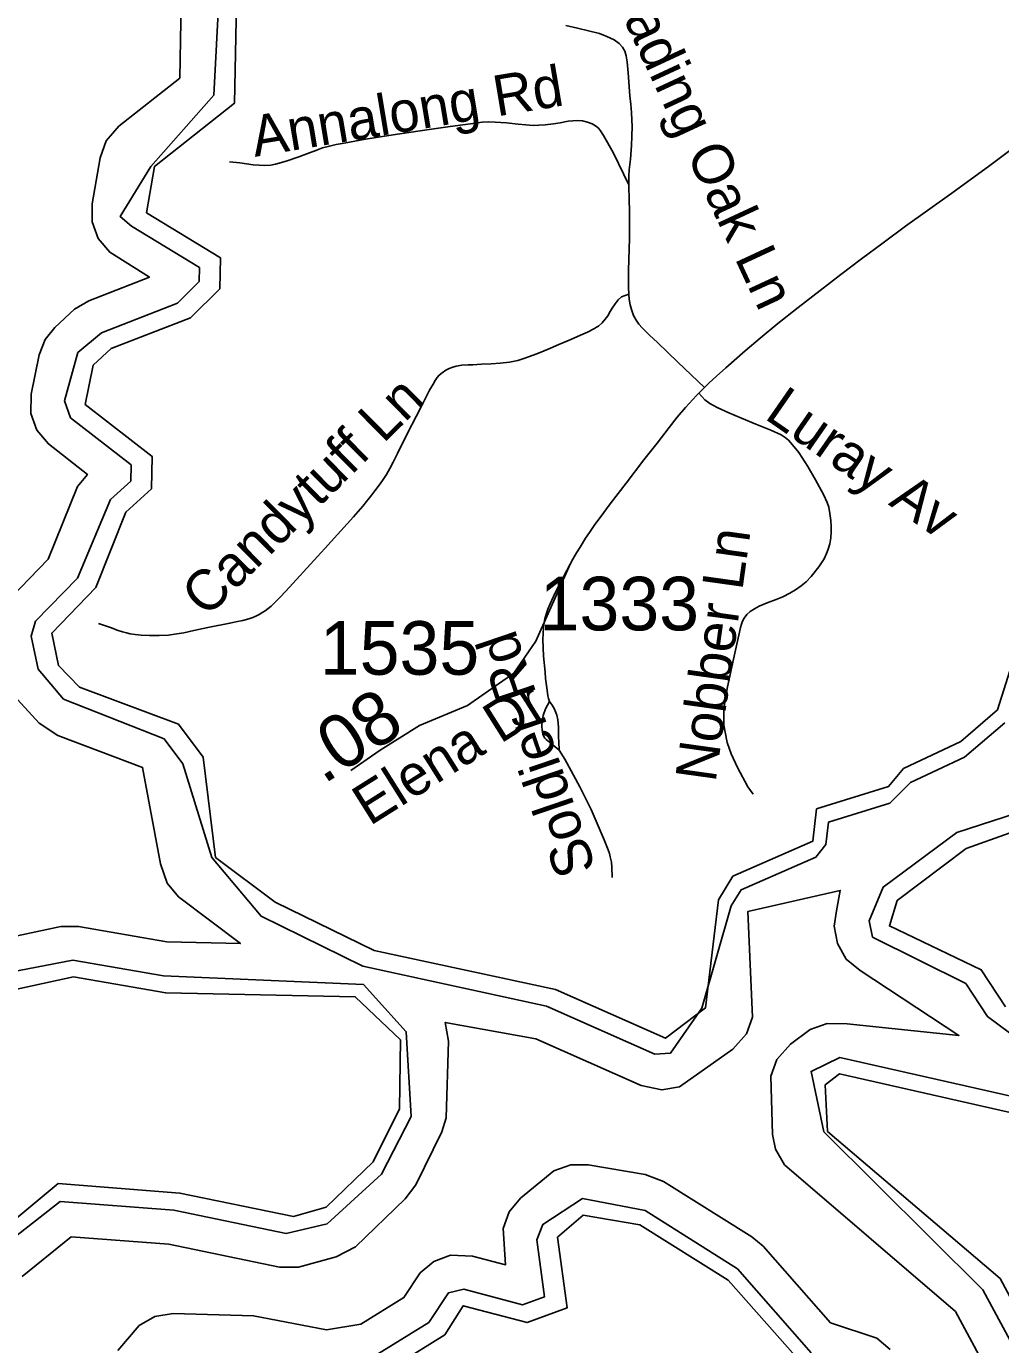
# Model space of a CAD drawing. Extents: x 1383679 to 1536984, y 460658 to 651027.
# Drawn here: x 1393235 to 1395507, y 499394 to 502468 of the extents above; entities that cross this region are included whole.
import ezdxf

# ---------------------------------------------------------------- set-up
doc = ezdxf.new("R2010")
doc.units = 0
for name, color, linetype in [('Exist Hydrographic Bay Label', 7, 'Continuous'), ('Exist Hydrographic Buffer Line', 7, 'Continuous'), ('Exist Hydrographic Island Shore', 7, 'Continuous'), ('Exist Road Non-System Type 51', 7, 'Continuous'), ('Exist Road Non-System Type 51 Label', 7, 'Continuous'), ('Exist Road Secondary Mileage Hundredths English Label', 7, 'Continuous'), ('Exist Road Secondary Type 51 Attributed', 7, 'Continuous'), ('Exist Road Secondary Type 51 Label', 7, 'Continuous'), ('Exist Road Secondary Type 51 Number Label', 7, 'Continuous')]:
    doc.layers.add(name, color=color, linetype=linetype)

msp = doc.modelspace()

# ---------------------------------------------------------------- linework, layer by layer
at = {"layer": 'Exist Hydrographic Bay Label'}
for points in [[(1395563, 501073.2), (1395500, 500874.2), (1395415, 500800.4), (1395281, 500737.4), (1395246, 500695.4), (1395078.1, 500643), (1395069.1, 500567.7), (1394883.1, 500486.1), (1394849.1, 500431), (1394819, 500178.8), (1394726, 500108.5), (1394469.1, 500222), (1394046.1, 500312.5), (1393815.1, 500425.5), (1393676.1, 500530), (1393647.1, 500763.7), (1393590.2, 500840.3), (1393359.2, 500927), (1393310.2, 500977.2), (1393294.2, 501053), (1393397.1, 501159.3), (1393467.2, 501335.1), (1393527.1, 501389.7), (1393528.2, 501465.2), (1393372.1, 501586.5), (1393391.2, 501678), (1393433.1, 501716.5), (1393618.2, 501788.3), (1393686.2, 501855.9), (1393688.1, 501928.1), (1393515.1, 502033.3), (1393534.1, 502141.2), (1393720.2, 502288.5), (1393725.1, 502521.4)], [(1395519.1, 500181.2), (1395462.1, 500267.7), (1395248.1, 500370.4), (1395266, 500429.2), (1395427, 500550.7), (1395628, 500622.1)], [(1395098.1, 499999.3), (1395132, 500024.9), (1395547, 499931.2)], [(1395610, 499355.4), (1395506, 499547.9), (1395104, 499890.9), (1395098.1, 499999.3)], [(1394067.1, 499327.4), (1394211.1, 499416.4), (1394254.1, 499484.5), (1394403.1, 499445.3), (1394496.1, 499479.6), (1394474, 499644.1), (1394534.1, 499695.5), (1394666.1, 499673.1), (1394872, 499544.3), (1395052.1, 499340.4)]]:
    msp.add_lwpolyline(points, dxfattribs=at)
at = {"layer": 'Exist Hydrographic Buffer Line'}
for points in [[(1393684.8, 502545.4), (1393672, 502307.8), (1393525.4, 502140.9), (1393454.2, 502024.5), (1393480.7, 502002.3), (1393638.8, 501905.6), (1393637.9, 501872.6), (1393587.3, 501822.2), (1393410, 501753.4), (1393355.5, 501707.1), (1393324.3, 501594.3), (1393337.7, 501555.4), (1393479.2, 501445.4), (1393478.7, 501407.2), (1393431.5, 501364.3), (1393354.2, 501181.1), (1393256.8, 501080.5), (1393246.2, 501045.7), (1393262.4, 500968.6), (1393321.9, 500898.7), (1393556.4, 500806.6), (1393600, 500747.9), (1393667.4, 500529.7), (1393782.4, 500393.1), (1394019.9, 500276.2), (1394448.1, 500183.3), (1394701.2, 500071.5), (1394737.4, 500073.4), (1394810.4, 500178.4), (1394879.1, 500417.1), (1394902, 500454), (1395076.6, 500530.7), (1395099.8, 500560.4), (1395106.1, 500612.2), (1395249.3, 500656.8), (1395297.4, 500704.5), (1395423.4, 500763.7), (1395517.6, 500843.6)], [(1393596.5, 502523.6), (1393592.7, 502347.2), (1393451, 502235), (1393421.5, 502200.8), (1393407.2, 502161.7), (1393388.3, 502053.7), (1393388.3, 502012.1), (1393402.5, 501972.9), (1393429.4, 501941), (1393522.3, 501882.9), (1393381.1, 501828), (1393347.4, 501808.1), (1393301.3, 501766), (1393278.6, 501737.6), (1393265, 501702.1), (1393246, 501610.6), (1393245.2, 501565.3), (1393259.5, 501526.1), (1393286.4, 501494.2), (1393377.5, 501423.2), (1393354.5, 501394.7), (1393285.7, 501225.4), (1393199.3, 501136.2)], [(1393197.6, 500916.9), (1393264.7, 500842.8), (1393308.4, 500814.3), (1393506.3, 500740), (1393548.3, 500514.9), (1393563.5, 500469.7), (1393590.3, 500437.8), (1393734.3, 500329.2), (1393563, 500333.3), (1393356.9, 500369), (1393315.7, 500368.9), (1393143.3, 500332.1)], [(1395758.5, 500868.4), (1396136.5, 500634.3), (1396309.1, 500617.1), (1396560.7, 500687.5), (1396631.7, 500686.1), (1396630.9, 500639.4), (1396553, 500590.9), (1396384.7, 500553.3), (1396292.2, 500488.1), (1396123.9, 500460), (1395914.6, 500591), (1395628.7, 500660.6), (1395405, 500587.9), (1395233.3, 500460.7), (1395201.2, 500381.7), (1395208.8, 500344.3), (1395426.2, 500236), (1395477, 500158.7), (1395634.1, 500042.3), (1395633.7, 500004.5), (1395538.1, 499971.8), (1395132.2, 500063.4)], [(1393225.5, 499552.9), (1393339.8, 499645.5), (1393567.7, 499627.8), (1393825.2, 499574.7), (1393870.2, 499574.1), (1393958, 499598.2), (1394002.6, 499621.8), (1394118.9, 499733.5), (1394143.2, 499766.8), (1394204.1, 499890.3), (1394214.6, 499922.5), (1394219.4, 500101.8), (1394212.3, 500145.2), (1394423.3, 500106.8), (1394668.9, 499998.3), (1394717.4, 499988.1), (1394758.4, 499995.3), (1394882.8, 500082.7), (1394914.4, 500118.4), (1394928.6, 500157.6), (1394917.8, 500403.5), (1395133.5, 500452.9), (1395124.8, 500405.1), (1395119.5, 500370), (1395126.7, 500328.9), (1395147.5, 500292.8), (1395179.5, 500266.1)], [(1394021.1, 500233.7), (1393555.3, 500253.5), (1393343.3, 500290.1), (1393152.8, 500253.7), (1393058.9, 500146.6)], [(1395179.5, 500266.1), (1395410.3, 500114.7), (1395149.9, 500141.5), (1395102.6, 500142.6), (1395063.4, 500128.3), (1395017.2, 500094.7), (1394985.5, 500058.8), (1394971.3, 500019.7), (1394975.6, 499883.9), (1394982.7, 499849.4), (1395003.5, 499813.3), (1395402.5, 499470.7), (1395495.8, 499298)], [(1393058.9, 500146.6), (1393022.9, 499595.5), (1393042.6, 499564.1), (1393174.1, 499617.7), (1393313.6, 499727.8), (1393578.9, 499707.2), (1393841.3, 499653.1), (1393936.4, 499675.2), (1394063.3, 499791.1), (1394132.3, 499925.6), (1394121, 500123.6), (1394021.1, 500233.7)], [(1395132.2, 500063.4), (1395065.4, 500030.8), (1395095.4, 499890.4)], [(1395095.4, 499890.4), (1395465.8, 499521.9), (1395566.2, 499336), (1395661.3, 499225.2), (1395907.7, 499135.9), (1395906, 499066.5), (1395873.7, 499018.1), (1395869.4, 498906.5), (1395958.8, 498720.2), (1396036.6, 498633.5)], [(1395250.1, 499382.3), (1395218.5, 499408.8), (1395110.9, 499444.8), (1394953.3, 499623.2), (1394927.1, 499645.5), (1394721.1, 499774.4), (1394678.3, 499790.9), (1394545.5, 499813.4), (1394504.7, 499813.2), (1394465.5, 499799), (1394387.5, 499735), (1394361.4, 499703.7), (1394347.2, 499664.6), (1394352.8, 499579.9), (1394275.9, 499600.1), (1394224.7, 499602.2), (1394185.5, 499588), (1394153.5, 499561.2), (1394115.8, 499503.5), (1394015.6, 499441.6), (1393935.1, 499428.3), (1393765.2, 499461), (1393577.8, 499466.5), (1393534.5, 499459.3), (1393498.4, 499438.4), (1393448.2, 499380.1)], [(1395065.9, 499374.9), (1394893.4, 499570.3), (1394678.7, 499706.6), (1394532.2, 499734.5), (1394439.5, 499674.1), (1394425.7, 499638.4), (1394443.6, 499505.6), (1394392.4, 499486.8), (1394255.6, 499522.8), (1394219.8, 499514.7), (1394173.5, 499445.2), (1394044.2, 499365.2)]]:
    msp.add_lwpolyline(points, dxfattribs=at)
at = {"layer": 'Exist Hydrographic Island Shore'}
msp.add_lwpolyline([(1393090.2, 499616.1), (1393174.1, 499657.1), (1393309.2, 499769.2), (1393593.2, 499747.2), (1393858.1, 499692.6), (1393934.1, 499714), (1394044.2, 499820.2), (1394105.1, 499943.7), (1394108.1, 500104.5), (1394002.1, 500205), (1393560.1, 500213.9), (1393345.2, 500251.1), (1393177.1, 500215.1), (1393109.1, 500147.5), (1393065.2, 499633.1), (1393090.2, 499616.1)], dxfattribs=at)
at = {"layer": 'Exist Road Non-System Type 51'}
for points in [[(1394493.4, 502469.7), (1394520.5, 502463.7), (1394546.2, 502457.7), (1394571.7, 502451), (1394589, 502444.6), (1394606.2, 502436.7), (1394617.6, 502428.2), (1394625.5, 502419.5), (1394630.7, 502409.7), (1394633.8, 502399.1), (1394636.6, 502385.4), (1394638.5, 502359.5), (1394642.9, 502306), (1394645.2, 502285.6), (1394646.4, 502267.1), (1394647.5, 502249.3), (1394647.9, 502234.7), (1394647.2, 502211.5), (1394646.4, 502190.3), (1394644, 502158.1), (1394641.4, 502133.2), (1394640.2, 502119.7), (1394640.2, 502098.2)], [(1393709, 502152.1), (1393733, 502149.4), (1393764.2, 502145.4), (1393778.3, 502144.2), (1393791, 502143.8), (1393805.1, 502144.6), (1393815.9, 502146.3), (1393841.1, 502153.3), (1393870.3, 502163.7), (1393895.5, 502172.7), (1393910.4, 502178.5), (1393926, 502184.3), (1393941.8, 502188.8), (1393957.6, 502192.4), (1393976.1, 502195.7), (1394025.9, 502204.9), (1394090.5, 502215), (1394169, 502226.7), (1394223.6, 502234.4), (1394282.8, 502242.5), (1394298, 502244.3), (1394313, 502245.2), (1394328.3, 502244.9), (1394355.1, 502242.9), (1394381.9, 502240.2), (1394400.2, 502238.1), (1394417.2, 502237.1), (1394430.7, 502237.3), (1394445.5, 502238.3), (1394464.8, 502240.8), (1394480.4, 502243.3), (1394498.8, 502246.6), (1394509.4, 502247.9), (1394521.1, 502248.3), (1394532.3, 502247.7), (1394544.1, 502244.9), (1394554.7, 502241), (1394562.6, 502236), (1394569.5, 502230.8), (1394574, 502224.4), (1394581.1, 502213.6), (1394604.1, 502173.7), (1394640.2, 502098.2)], [(1394640.2, 502098.2), (1394640.2, 502095.4), (1394641.4, 502063.8), (1394641.7, 502037.2), (1394641.6, 501973.5), (1394639.5, 501899.3), (1394639.4, 501872.1), (1394639.4, 501860.1), (1394640.2, 501843.2)], [(1394640.2, 501843.2), (1394631.6, 501840.5), (1394623.5, 501837), (1394615.4, 501830.1), (1394608.2, 501821.2), (1394601.2, 501810.8), (1394596.6, 501802.7), (1394591, 501793.2), (1394585.4, 501785.3), (1394578.1, 501776.4), (1394569.4, 501769.1), (1394565.2, 501766.4), (1394560.3, 501763.3), (1394543.7, 501754.9), (1394527.9, 501747.5), (1394505.1, 501737.9), (1394477.2, 501725.9), (1394457.7, 501717.8), (1394437.4, 501709.3), (1394423.3, 501703.6), (1394408.7, 501698), (1394395.4, 501693.5), (1394381.1, 501689), (1394361.6, 501685), (1394340, 501682.3), (1394318.9, 501680.6), (1394296.7, 501679.8), (1394276.3, 501678.9), (1394265.7, 501678.6), (1394250.7, 501677.7), (1394237.3, 501675.8), (1394229.9, 501673.4), (1394221, 501670), (1394213.3, 501666.1), (1394204.8, 501660.3), (1394198.2, 501654.2), (1394193.2, 501648.8), (1394188.6, 501641.8), (1394183.6, 501633.7), (1394175.5, 501619.8), (1394168.1, 501605.2), (1394155, 501579.3), (1394144.2, 501558.5), (1394124.9, 501521.1), (1394101, 501472.2), (1394096.4, 501462.9), (1394090.6, 501451.3), (1394083.2, 501437), (1394074.7, 501423.1), (1394065.9, 501408.9), (1394058.2, 501398.1), (1394048.1, 501384.6), (1394040.8, 501375.3), (1394028.8, 501359.9), (1394019.6, 501349.1), (1393998.2, 501324.5), (1393931, 501250.3), (1393913.8, 501231.3), (1393840.5, 501150.7), (1393826.4, 501136), (1393820.2, 501129.6), (1393812.5, 501121.9), (1393806.3, 501116.1), (1393799.3, 501110.3), (1393792.3, 501105.3), (1393786.5, 501101.5), (1393778.4, 501096.8), (1393770.3, 501092.6), (1393763, 501089.5), (1393754.1, 501086.4), (1393739.8, 501082.6), (1393723.4, 501079), (1393709.7, 501076.1), (1393658.6, 501066), (1393625.4, 501059.1), (1393602.7, 501054), (1393586.1, 501051.3), (1393566.4, 501048.6), (1393545.2, 501047.1), (1393522.2, 501047.2), (1393502.8, 501048), (1393488.8, 501049.4), (1393476.9, 501051.3), (1393468.4, 501053.6), (1393459.5, 501056.3), (1393449.5, 501059.4), (1393431, 501066), (1393403.2, 501075.2)], [(1394640.2, 501843.2), (1394641.4, 501831.6), (1394643.6, 501818.9), (1394643.7, 501818.5), (1394646.4, 501807.7), (1394651.4, 501793.4), (1394657.2, 501783), (1394663.7, 501773.4), (1394671.2, 501764.8), (1394688.4, 501747.9), (1394707.3, 501730.6), (1394730.9, 501707.4), (1394754.3, 501684.6), (1394816.5, 501625.8)], [(1394803.8, 501612.4), (1394817.9, 501597), (1394828.9, 501588.6), (1394846.7, 501579.1), (1394873.8, 501566.4), (1394902.8, 501554), (1394936.7, 501540.4), (1394971.2, 501526.1), (1394995.5, 501515.1), (1395005.2, 501509.3), (1395012.5, 501502.6), (1395022.3, 501492.1), (1395037, 501474.2), (1395057.8, 501441.6), (1395076, 501410.2), (1395094.3, 501375.9), (1395103, 501357.4), (1395106.8, 501346.6), (1395109.3, 501332.3), (1395111.6, 501315.3), (1395112.6, 501302), (1395112.6, 501288.9), (1395111.4, 501275.4), (1395109.1, 501261), (1395104.9, 501248.6), (1395101.4, 501238.8), (1395095.6, 501226.3), (1395083.3, 501207.8), (1395065.2, 501184.8), (1395053.6, 501172.9), (1395042.4, 501163.2), (1395029.3, 501154.2), (1395015.6, 501146.1), (1394999.4, 501137.6), (1394984, 501131.2), (1394963.1, 501123.7), (1394944.6, 501115.8), (1394933.4, 501110), (1394923, 501103.8), (1394915.7, 501096.1), (1394909.3, 501088), (1394905.7, 501080.5), (1394902.8, 501073.6), (1394900.8, 501066), (1394897.1, 501048.2), (1394884.5, 500992.6), (1394870.3, 500927.8), (1394864.9, 500897.3), (1394862.7, 500881), (1394861.8, 500867), (1394861.6, 500852.2), (1394862, 500838.2), (1394864.9, 500822.3), (1394869.9, 500797.7), (1394878.8, 500771.5), (1394893.4, 500739.3), (1394917.8, 500694.4), (1394930.1, 500677.1)], [(1394503.2, 501213.6), (1394495.4, 501199.1), (1394480, 501169.2), (1394469.6, 501148.4), (1394464.9, 501138.5), (1394456.8, 501121.1), (1394451.4, 501108.8), (1394447.9, 501099.9)], [(1394447.9, 501099.9), (1394444.4, 501086.3), (1394442.6, 501077.8), (1394441, 501066), (1394439.9, 501038.2), (1394441.3, 500999.3), (1394444.8, 500962.2), (1394446.2, 500947.5), (1394449.7, 500920.2), (1394451.6, 500907), (1394452.8, 500900.5), (1394455, 500893.4)], [(1394455, 500893.4), (1394446, 500876.6), (1394440.2, 500861.2), (1394437.9, 500848.6), (1394437.6, 500836.1), (1394438.1, 500826.8), (1394440, 500817.6), (1394442, 500812.2), (1394444.3, 500808.3), (1394447.2, 500805.2), (1394447.2, 500805.1), (1394459.1, 500795.6), (1394477.5, 500779.8)], [(1394455, 500893.4), (1394461.6, 500884.7), (1394465.9, 500877.3), (1394470.1, 500867.7), (1394472.1, 500861.9), (1394474.4, 500850.7), (1394475.5, 500842.6), (1394475.9, 500833.8), (1394475.9, 500825.3), (1394475.9, 500819.5), (1394476.3, 500810.2), (1394476.7, 500799.8), (1394477.5, 500779.8)], [(1394477.5, 500779.8), (1394491, 500758.9), (1394525.7, 500694.6), (1394552.1, 500642), (1394583.1, 500570.6), (1394592.1, 500548), (1394595.2, 500539.1), (1394597.1, 500531.4), (1394599.8, 500519), (1394600.4, 500507.6), (1394601.3, 500483.4)]]:
    msp.add_lwpolyline(points, dxfattribs=at)
at = {"layer": 'Exist Road Secondary Type 51 Attributed'}
for points in [[(1395547.7, 502192.6), (1395482.5, 502143.8), (1395393.6, 502078.8), (1395285.9, 502001.7), (1395233.7, 501963.1), (1395182.9, 501925.8), (1395135, 501889.2), (1395086.2, 501851.8), (1395035, 501812.1), (1394988.1, 501774.8), (1394946.7, 501741), (1394911.3, 501711.6), (1394866.2, 501671.7), (1394845.1, 501652.2), (1394827, 501635.6), (1394803.8, 501612.4), (1394798.4, 501607), (1394772.3, 501579.1), (1394753, 501556.3), (1394734.7, 501532.8), (1394706.1, 501495.7), (1394675.6, 501456.9), (1394634.1, 501403), (1394596.7, 501354.2), (1394573.4, 501322.6), (1394561.3, 501306.1), (1394548.5, 501288), (1394539.5, 501274.5), (1394526.7, 501253.4), (1394518.4, 501240), (1394509.6, 501225.2), (1394503.2, 501213.6), (1394423.1, 501034.5), (1394372.1, 500959.3)], [(1394372.1, 500959.3), (1394263.7, 500884.4), (1394152.1, 500837.9), (1394060.2, 500779.9), (1393991.8, 500732.7)]]:
    msp.add_lwpolyline(points, dxfattribs=at)

# ---------------------------------------------------------------- texts
at = {"layer": 'Exist Road Non-System Type 51 Label'}
for s, rotation, p in [('Spreading Oak Ln', 294.914, (1394514.5, 502728.7)), ('Annalong Rd', 9.4696, (1393768, 502163.5)), ('Candytuff Ln', 44.6158, (1393655.3, 501086.9)), ('Luray Av', 325.219, (1394953.9, 501554.9)), ('Nobber Ln', 82.0595, (1394842.5, 500703.2)), ('Soldier Rd', 108.7917, (1394564.4, 500503.8))]:
    msp.add_text(s, height=95, rotation=rotation, dxfattribs=at).set_placement(p)
at = {"layer": 'Exist Road Secondary Mileage Hundredths English Label'}
msp.add_text('.08', height=125, rotation=33.2728, dxfattribs=at).set_placement((1393928.2, 500699.2))
at = {"layer": 'Exist Road Secondary Type 51 Label'}
msp.add_text('Elena Dr', height=95, rotation=32.1761, dxfattribs=at).set_placement((1394035.8, 500602.2))
at = {"layer": 'Exist Road Secondary Type 51 Number Label'}
for s, p in [('1333', (1394432.2, 501059.4)), ('1535', (1393919.5, 500955.9))]:
    msp.add_text(s, height=125, dxfattribs=at).set_placement(p)

doc.saveas('drawing.dxf')
